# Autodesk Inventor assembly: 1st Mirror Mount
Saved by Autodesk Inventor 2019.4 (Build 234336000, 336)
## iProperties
Created: 2019-10
Part Number: 1st Mirror Mount
Document SubType Name: Assembly
Designer: Administrator
Title: 1st Mirror Mount v3
Author: Administrator
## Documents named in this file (11)
- c:\worker\convert-fusion-r07\tmp\job-1\6\output\files\671c8872-2f2e-4281-8226-91d9df48de79\069bd6d5-a2c2-468d-aee2-0432df35f21c.iam
- c:\worker\convert-fusion-r07\tmp\job-1\6\output\files\671c8872-2f2e-4281-8226-91d9df48de79\Base.ipt
- c:\worker\convert-fusion-r07\tmp\job-1\6\output\files\671c8872-2f2e-4281-8226-91d9df48de79\Mirror_base.ipt
- c:\worker\convert-fusion-r07\tmp\job-1\6\output\files\671c8872-2f2e-4281-8226-91d9df48de79\Mirror_nut.ipt
- c:\worker\convert-fusion-r07\tmp\job-1\6\output\files\671c8872-2f2e-4281-8226-91d9df48de79\Mirror_base_holder.ipt
- c:\worker\convert-fusion-r07\tmp\job-1\6\output\files\671c8872-2f2e-4281-8226-91d9df48de79\Crosshair_mount.ipt
- c:\worker\convert-fusion-r07\tmp\job-1\6\output\files\671c8872-2f2e-4281-8226-91d9df48de79\Base_screw.ipt
- c:\worker\convert-fusion-r07\tmp\job-1\6\output\files\671c8872-2f2e-4281-8226-91d9df48de79\Base_screw (1).ipt
- c:\worker\convert-fusion-r07\tmp\job-1\6\output\files\671c8872-2f2e-4281-8226-91d9df48de79\Crosshair_screw.ipt
- c:\worker\convert-fusion-r07\tmp\job-1\6\output\files\671c8872-2f2e-4281-8226-91d9df48de79\Counter_base_screw.ipt
- c:\worker\convert-fusion-r07\tmp\job-1\6\output\files\671c8872-2f2e-4281-8226-91d9df48de79\Position_base_screw.ipt
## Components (14 placed, 10 different names)
1. Base:1
2. Mirror_base:1
3. Mirror_nut:1
4. Mirror_base_holder:1
5. Crosshair_mount:1
6. Base_screw:1
7. Base_screw (1):1
8. Crosshair_screw:1
9. Crosshair_screw:2
10. Counter_base_screw:1
11. Position_base_screw:1
12. Position_base_screw:4
13. Position_base_screw:5
14. Counter_base_screw:2
